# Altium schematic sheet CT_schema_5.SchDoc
size 207 x 169 mm
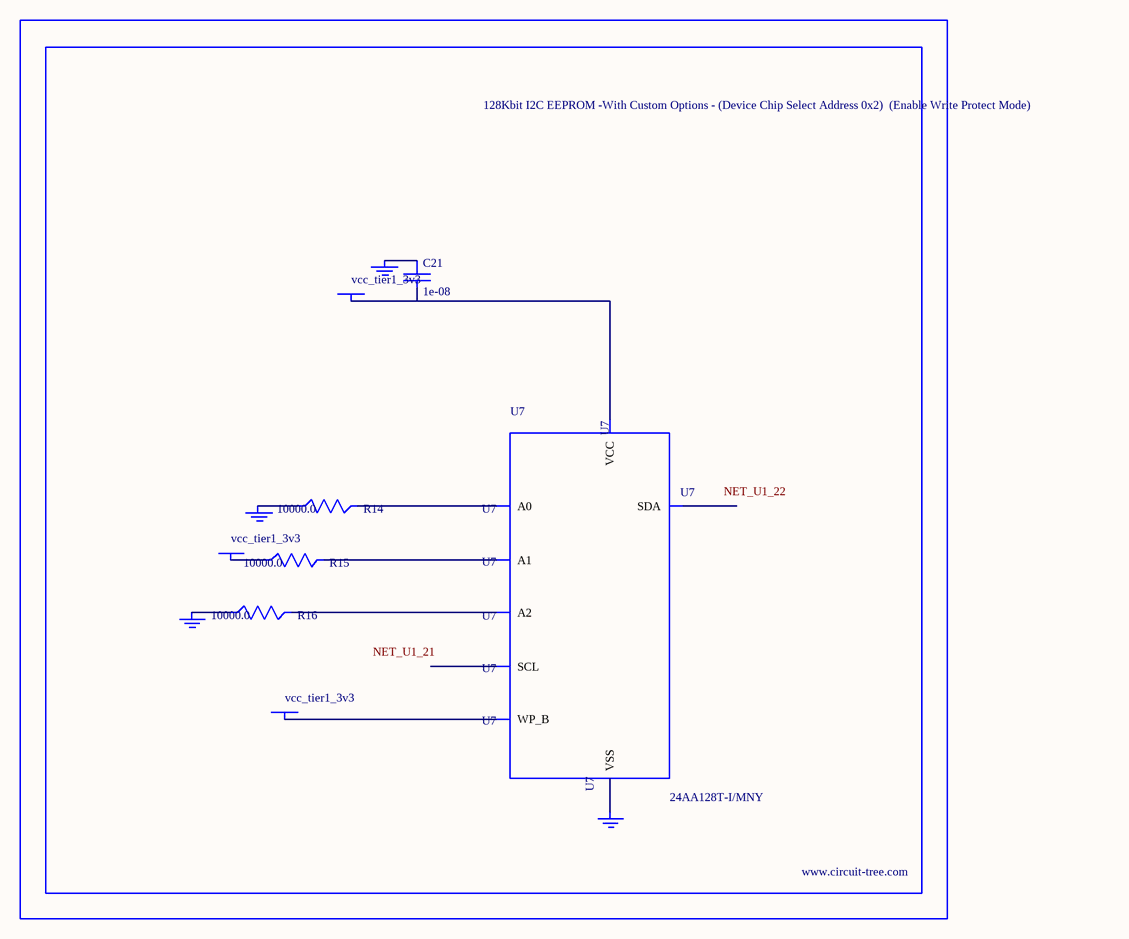
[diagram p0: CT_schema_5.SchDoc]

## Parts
BORDER4  (no value)
C21  1e-08  [C0402]
GND_INSTANCE_4_0  (no value)
GND_INSTANCE_4_1  (no value)
GND_INSTANCE_4_2  (no value)
GND_INSTANCE_4_3  (no value)
POWER_INSTANCE_4_0  vcc_tier1_3v3
POWER_INSTANCE_4_1  vcc_tier1_3v3
POWER_INSTANCE_4_2  vcc_tier1_3v3
R14  10000.0  [R0603]
R15  10000.0  [R0603]
R16  10000.0  [R0603]
U7  24AA128T-I/MNY  [TDFN-8/6MM]

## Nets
NetC21_1: C21.1 GND_INSTANCE_4_2.0(GND)
NetC21_2: C21.2 POWER_INSTANCE_4_2.0(PWR) U7.8(VCC)
NetGND_INSTANCE_4_0_0: GND_INSTANCE_4_0.0(GND) R14.1
NetGND_INSTANCE_4_1_0: GND_INSTANCE_4_1.0(GND) R16.1
NetGND_INSTANCE_4_3_0: GND_INSTANCE_4_3.0(GND) U7.4(VSS)
NetPOWER_INSTANCE_4_0_0: POWER_INSTANCE_4_0.0(PWR) R15.1
NetPOWER_INSTANCE_4_1_0: POWER_INSTANCE_4_1.0(PWR) U7.7(WP_B)
NetR14_2: R14.2 U7.1(A0)
NetR15_2: R15.2 U7.2(A1)
NetR16_2: R16.2 U7.3(A2)

Not connected (* = marked no-connect by the designer): U7 5(SDA) 6(SCL)

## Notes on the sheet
- Labels drawn without touching a wire or pin: NET_U1_21, NET_U1_22

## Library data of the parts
BORDER4 = BORDER_PAGE4
C21 = C0402C103K3RAC
GND_INSTANCE_4_0-GND_INSTANCE_4_3 = GND
POWER_INSTANCE_4_0-POWER_INSTANCE_4_2 = PWR
R14-R16 = RC0603JR-0710KL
